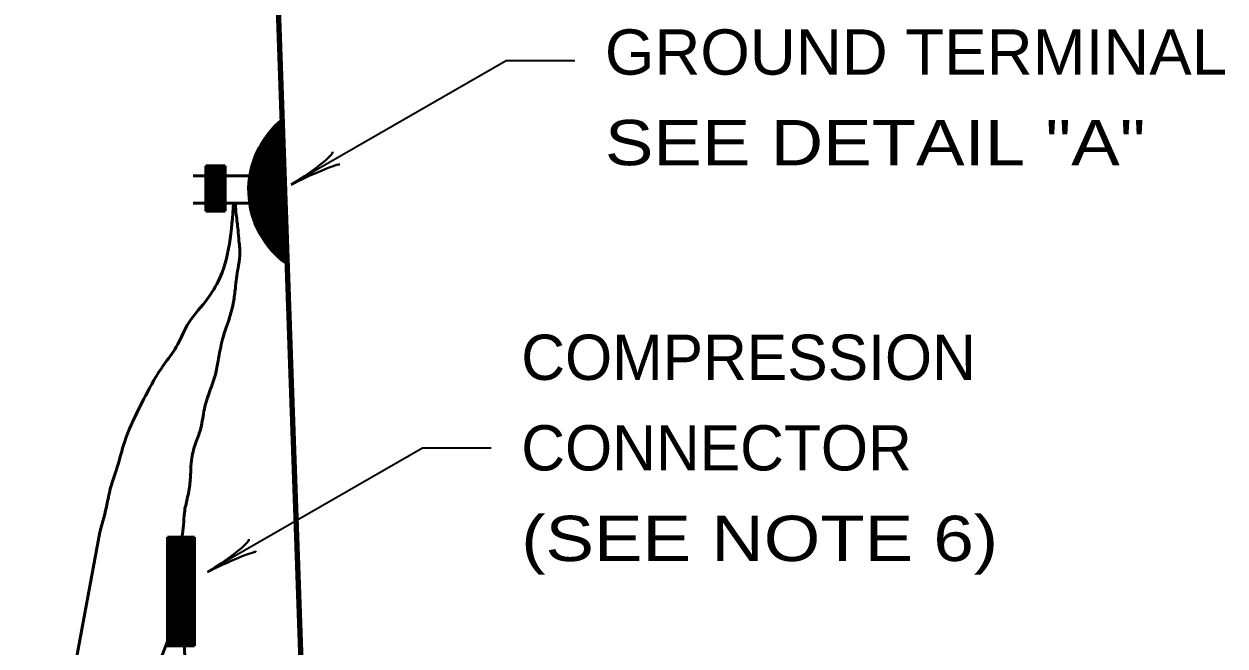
# Model space of a CAD drawing. Extents: x -153 to 527, y -247 to 194.
# Drawn here: x 120.6 to 186.8, y 96.8 to 131.2 of the extents above; entities that cross this region are included whole.
import ezdxf

# ---------------------------------------------------------------- set-up
doc = ezdxf.new("R2010")
doc.units = 0
doc.layers.add('1', color=7, linetype='Continuous', lineweight=53)

msp = doc.modelspace()

# ---------------------------------------------------------------- linework, layer by layer
at = {"layer": '1', "lineweight": 90}
msp.add_line((136.438, 80.231), (133.611, 161.182), dxfattribs=at)
at = {"layer": '1'}
for p, q in [((134.982, 118.116), (134.633, 125.596)), ((134.715, 125.719), (135.023, 118.116)), ((130.619, 123.329), (130.619, 120.829)), ((130.619, 123.329), (131.686, 123.329)), ((130.619, 123.306), (131.686, 123.306)), ((130.619, 123.299), (131.686, 123.299)), ((130.619, 123.281), (131.686, 123.281)), ((130.619, 123.243), (131.686, 123.243)), ((130.619, 123.237), (131.686, 123.237)), ((131.686, 123.329), (131.686, 120.829)), ((133.05, 122.781), (129.927, 122.781)), ((130.619, 123.212), (131.686, 123.212)), ((130.619, 123.193), (131.686, 123.193)), ((130.619, 123.193), (131.686, 123.193)), ((130.619, 123.168), (131.686, 123.168)), ((130.619, 123.162), (131.686, 123.162)), ((130.619, 123.162), (131.686, 123.162)), ((130.619, 123.149), (131.686, 123.149)), ((130.619, 123.137), (131.686, 123.137)), ((130.619, 123.124), (131.686, 123.124)), ((130.619, 123.105), (131.686, 123.105)), ((130.619, 123.08), (131.686, 123.08)), ((130.619, 123.074), (131.686, 123.074)), ((130.619, 123.068), (131.686, 123.068)), ((130.619, 123.036), (131.686, 123.036)), ((130.619, 123.024), (131.686, 123.024)), ((130.619, 123.024), (131.686, 123.024)), ((130.619, 123.011), (131.686, 123.011)), ((130.619, 123.005), (131.686, 123.005)), ((130.619, 122.999), (131.686, 122.999)), ((130.619, 122.999), (131.686, 122.999)), ((130.619, 122.98), (131.686, 122.98)), ((130.619, 122.961), (131.686, 122.961)), ((130.619, 122.961), (131.686, 122.961)), ((130.619, 122.949), (131.686, 122.949)), ((130.619, 122.923), (131.686, 122.923)), ((130.619, 122.923), (131.686, 122.923)), ((130.619, 122.905), (131.686, 122.905)), ((130.619, 122.892), (131.686, 122.892)), ((130.619, 122.892), (131.686, 122.892)), ((130.619, 122.867), (131.686, 122.867)), ((130.619, 122.867), (131.686, 122.867)), ((130.619, 122.842), (131.686, 122.842)), ((130.619, 122.836), (131.686, 122.836)), ((130.619, 122.836), (131.686, 122.836)), ((130.619, 122.817), (131.686, 122.817)), ((130.619, 122.811), (131.686, 122.811)), ((130.619, 122.792), (131.686, 122.792)), ((130.619, 122.786), (131.686, 122.786)), ((130.619, 122.754), (131.686, 122.754)), ((130.619, 122.748), (131.686, 122.748)), ((130.619, 122.742), (131.686, 122.742)), ((130.619, 122.742), (131.686, 122.742)), ((130.619, 122.729), (131.686, 122.729)), ((130.619, 122.692), (131.686, 122.692)), ((130.619, 122.692), (131.686, 122.692)), ((130.619, 122.685), (131.686, 122.685)), ((130.619, 122.685), (131.686, 122.685)), ((130.619, 122.667), (131.686, 122.667)), ((130.619, 122.635), (131.686, 122.635)), ((130.619, 122.635), (131.686, 122.635)), ((130.619, 122.623), (131.686, 122.623)), ((130.619, 122.591), (131.686, 122.591)), ((130.619, 122.56), (131.686, 122.56)), ((130.619, 122.529), (131.686, 122.529)), ((130.619, 122.516), (131.686, 122.516)), ((130.619, 122.504), (131.686, 122.504)), ((130.619, 122.485), (131.686, 122.485)), ((130.619, 122.453), (131.686, 122.453)), ((130.619, 122.422), (131.686, 122.422)), ((130.619, 122.41), (131.686, 122.41)), ((130.619, 122.385), (131.686, 122.385)), ((130.619, 122.385), (131.686, 122.385)), ((130.619, 122.366), (131.686, 122.366)), ((130.619, 122.347), (131.686, 122.347)), ((130.619, 122.341), (131.686, 122.341)), ((130.619, 122.322), (131.686, 122.322)), ((130.619, 122.322), (131.686, 122.322)), ((130.619, 122.284), (131.686, 122.284)), ((130.619, 122.278), (131.686, 122.278)), ((130.619, 122.247), (131.686, 122.247)), ((130.619, 122.234), (131.686, 122.234)), ((130.619, 122.222), (131.686, 122.222)), ((130.619, 122.184), (131.686, 122.184)), ((130.619, 122.184), (131.686, 122.184)), ((130.619, 122.146), (131.686, 122.146)), ((130.619, 122.128), (131.686, 122.128)), ((130.619, 122.115), (131.686, 122.115)), ((130.619, 122.09), (131.686, 122.09)), ((130.619, 122.09), (131.686, 122.09)), ((130.619, 122.059), (131.686, 122.059)), ((130.619, 122.034), (131.686, 122.034)), ((130.619, 121.996), (131.686, 121.996)), ((130.619, 121.965), (131.686, 121.965)), ((130.619, 121.927), (131.686, 121.927)), ((130.619, 121.908), (131.686, 121.908)), ((133.04, 121.281), (129.927, 121.281)), ((130.619, 121.883), (131.686, 121.883)), ((130.619, 121.852), (131.686, 121.852)), ((130.619, 121.833), (131.686, 121.833)), ((130.619, 121.796), (131.686, 121.796)), ((130.619, 121.77), (131.686, 121.77)), ((130.619, 121.752), (131.686, 121.752)), ((130.619, 121.733), (131.686, 121.733)), ((130.619, 121.733), (131.686, 121.733)), ((130.619, 121.708), (131.686, 121.708)), ((130.619, 121.689), (131.686, 121.689)), ((130.619, 121.689), (131.686, 121.689)), ((130.619, 121.67), (131.686, 121.67)), ((130.619, 121.645), (131.686, 121.645)), ((130.619, 121.639), (131.686, 121.639)), ((130.619, 121.608), (131.686, 121.608)), ((130.619, 121.608), (131.686, 121.608)), ((130.619, 121.595), (131.686, 121.595)), ((130.619, 121.589), (131.686, 121.589)), ((130.619, 121.57), (131.686, 121.57)), ((130.619, 121.551), (131.686, 121.551)), ((130.619, 121.551), (131.686, 121.551)), ((130.619, 121.526), (131.686, 121.526)), ((130.619, 121.507), (131.686, 121.507)), ((130.619, 121.476), (131.686, 121.476)), ((130.619, 121.451), (131.686, 121.451)), ((130.619, 121.432), (131.686, 121.432)), ((130.619, 121.42), (131.686, 121.42)), ((130.619, 121.401), (131.686, 121.401)), ((130.619, 121.37), (131.686, 121.37)), ((130.619, 121.338), (131.686, 121.338)), ((130.619, 121.313), (131.686, 121.313)), ((130.619, 121.3), (131.686, 121.3)), ((130.619, 121.294), (131.686, 121.294)), ((130.619, 121.257), (131.686, 121.257)), ((130.619, 121.225), (131.686, 121.225)), ((130.619, 121.188), (131.686, 121.188)), ((130.619, 121.169), (131.686, 121.169)), ((130.619, 121.125), (131.686, 121.125)), ((130.619, 121.106), (131.686, 121.106)), ((130.619, 121.094), (131.686, 121.094)), ((130.619, 121.056), (131.686, 121.056)), ((130.619, 121.031), (131.686, 121.031)), ((130.619, 120.993), (131.686, 120.993)), ((130.619, 120.975), (131.686, 120.975)), ((130.619, 120.95), (131.686, 120.95)), ((130.619, 120.925), (131.686, 120.925)), ((130.619, 120.893), (131.686, 120.893)), ((130.619, 120.887), (131.686, 120.887)), ((130.619, 120.868), (131.686, 120.868)), ((130.619, 120.843), (131.686, 120.843)), ((130.619, 120.829), (131.686, 120.829)), ((130.006, 102.832), (128.506, 102.832)), ((128.631, 102.832), (128.631, 96.832)), ((128.731, 102.832), (128.731, 96.832)), ((128.806, 102.832), (128.806, 96.832)), ((128.856, 102.832), (128.856, 96.832)), ((128.957, 102.832), (128.957, 96.832)), ((129.032, 102.832), (129.032, 96.832)), ((129.082, 102.832), (129.082, 96.832)), ((129.182, 102.832), (129.182, 96.832)), ((129.182, 102.832), (129.182, 96.832)), ((129.233, 102.832), (129.233, 96.832)), ((129.333, 102.832), (129.333, 96.832)), ((129.333, 102.832), (129.333, 96.832)), ((129.383, 102.832), (129.383, 96.832)), ((129.506, 96.832), (129.506, 102.832)), ((129.571, 96.832), (129.571, 102.832)), ((129.634, 96.832), (129.634, 102.832)), ((129.685, 96.832), (129.685, 102.832)), ((129.748, 96.832), (129.748, 102.832)), ((129.799, 96.832), (129.799, 102.832)), ((129.875, 96.832), (129.875, 102.832)), ((129.913, 96.832), (129.913, 102.832)), ((130.006, 102.832), (130.006, 96.832)), ((124.878, 87.628), (128.635, 97.416)), ((129.637, 86.475), (129.457, 96.835))]:
    msp.add_line(p, q, dxfattribs=at)
at = {"layer": '1', "lineweight": 35}
for points in [[(150.986, 129.139), (147.188, 129.139), (135.34, 122.3)], [(146.372, 107.748), (142.574, 107.748), (130.726, 100.909)]]:
    msp.add_lwpolyline(points, dxfattribs=at)
at = {"layer": '1'}
for points in [[(134.53, 125.534), (134.9, 118.157), (134.448, 125.493), (134.818, 118.218), (134.365, 125.308), (134.735, 118.301), (134.242, 125.226), (134.633, 118.383), (134.283, 125.206), (134.53, 118.506), (134.139, 125.103), (134.427, 118.547), (134.119, 125.041), (134.324, 118.691), (135.085, 118.033), (134.201, 118.794), (133.996, 124.959), (134.653, 125.596), (134.037, 124.856), (134.222, 118.958)], [(134.098, 119.02), (133.913, 124.753), (134.098, 118.958), (133.831, 124.651), (134.016, 119.061), (134.304, 118.794)], [(133.934, 119.164), (133.646, 124.363), (133.831, 119.308), (133.543, 124.24), (133.749, 119.492), (133.482, 123.993), (133.646, 119.657), (133.379, 123.808), (133.543, 119.862), (133.256, 123.541), (133.441, 120.088), (133.194, 123.171), (133.358, 120.417), (133.132, 122.883), (133.276, 120.561), (133.05, 122.513), (133.174, 120.952), (133.297, 123.5)], [(134.263, 118.938), (133.954, 119.205), (133.749, 124.527), (133.954, 119.225)], [(133.317, 122.76), (133.05, 121.794), (133.317, 120.438), (133.687, 119.739), (133.872, 119.308)], [(128.506, 102.832), (128.506, 96.832), (130.006, 96.832)]]:
    msp.add_lwpolyline(points, dxfattribs=at)
msp.add_arc((137.976, 121.999), 4.988, 128.68208, 235.31633, dxfattribs=at)
at = {"layer": '1', "lineweight": 40}
for centre, major_axis, ratio, start_param, end_param in [((136.147, 123.085), (-1.468, -1.028), 0.122415, 0.896353, 3.141593), ((136.147, 123.085), (-1.468, -1.028), 0.122415, 0.896353, 3.141593), ((136.416, 122.677), (1.609, 0.726), 0.07063, 6.282307, 8.559703), ((136.416, 122.677), (1.609, 0.726), 0.07063, 6.282307, 8.559703), ((131.533, 101.693), (-1.468, -1.028), 0.122415, 0.896353, 3.141593), ((131.533, 101.693), (-1.468, -1.028), 0.122415, 0.896353, 3.141593), ((131.803, 101.285), (1.609, 0.726), 0.07063, 6.282307, 8.559703), ((131.803, 101.285), (1.609, 0.726), 0.07063, 6.282307, 8.559703)]:
    msp.add_ellipse(centre, major_axis=major_axis, ratio=ratio, start_param=start_param, end_param=end_param, dxfattribs=at)
at = {"layer": '1'}
for points in [[(132.149, 121.281), (131.303, 116.943), (130.601, 115.841), (129.599, 114.537), (128.997, 113.334), (128.296, 112.332), (127.293, 110.628), (126.692, 109.425), (126.09, 107.921), (125.689, 106.518), (125.388, 105.615), (125.188, 104.713), (124.787, 103.109)], [(132.255, 121.242), (132.247, 121.254), (132.247, 121.275)], [(132.255, 121.242), (132.305, 120.64), (132.406, 119.788), (132.456, 119.187), (132.506, 118.385), (132.406, 117.683), (132.255, 116.58), (132.155, 115.828), (131.955, 115.026), (131.554, 113.773), (131.303, 112.57), (131.153, 111.819), (130.852, 110.916), (130.551, 109.914), (130.351, 108.861), (130.1, 108.109), (129.849, 107.207), (129.799, 106.606), (129.749, 105.804), (129.599, 104.952), (129.448, 104.2), (129.398, 103.498), (129.298, 102.846), (129.198, 102.546)], [(120.597, 77.275), (121.98, 87.17), (124.787, 103.109)]]:
    msp.add_spline(points, degree=3, dxfattribs=at)

# ---------------------------------------------------------------- texts
for s, width, p in [('GROUND TERMINAL', 1.05, (152.642, 128.369)), ('SEE DETAIL "A"', 1.2, (152.642, 123.369)), ('(SEE NOTE 6)', 1.2, (148.029, 101.514))]:
    msp.add_text(s, height=2.5, dxfattribs=dict(at, width=width)).set_placement(p)
for s, p in [('COMPRESSION', (148.029, 111.514)), ('CONNECTOR', (148.029, 106.514))]:
    msp.add_text(s, height=2.5, dxfattribs=at).set_placement(p)

doc.saveas('drawing.dxf')
